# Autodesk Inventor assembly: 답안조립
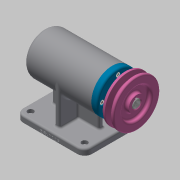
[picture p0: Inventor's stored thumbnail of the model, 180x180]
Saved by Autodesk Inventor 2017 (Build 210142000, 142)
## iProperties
Part Number: 답안조립
Material: 일반
Document SubType Name: Assembly
Designer: mrc
Mass: 2116.18 g
Surface Area: 1390.5 cm^2
Volume: 539.668 cm^3
Density: 3.92126 g/cm^3
Author: mrc
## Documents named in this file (12)
- C:\Users\mrc\Desktop\701004V1033\답안조립.iam
- C:\Users\mrc\Desktop\701004V1033\본체.ipt
- C:\Users\mrc\Desktop\701004V1033\V벨트풀리.ipt
- C:\Users\mrc\Desktop\701004V1033\멈춤나사 M3.ipt
- C:\Users\mrc\Desktop\701004V1033\베어링 6004.ipt
- C:\Users\mrc\Desktop\701004V1033\베어링 51202.ipt
- C:\Users\mrc\Desktop\701004V1033\볼트 M4.ipt
- C:\Users\mrc\Desktop\701004V1033\어댑터슬리브.ipt
- C:\Users\mrc\Desktop\701004V1033\오일 실.ipt
- C:\Users\mrc\Desktop\701004V1033\축.ipt
- C:\Users\mrc\Desktop\701004V1033\커버.ipt
- C:\Users\mrc\Desktop\701004V1033\키 5 x 5 x 16.ipt
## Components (1 placed, 1 different names)
1. V벨트풀리:1 — 플러쉬:1, 각도:1
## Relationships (2: Flush 1, Angle 1)
- 플러쉬:1 [Flush]: V벨트풀리:1
- 각도:1 [Angle]: V벨트풀리:1
